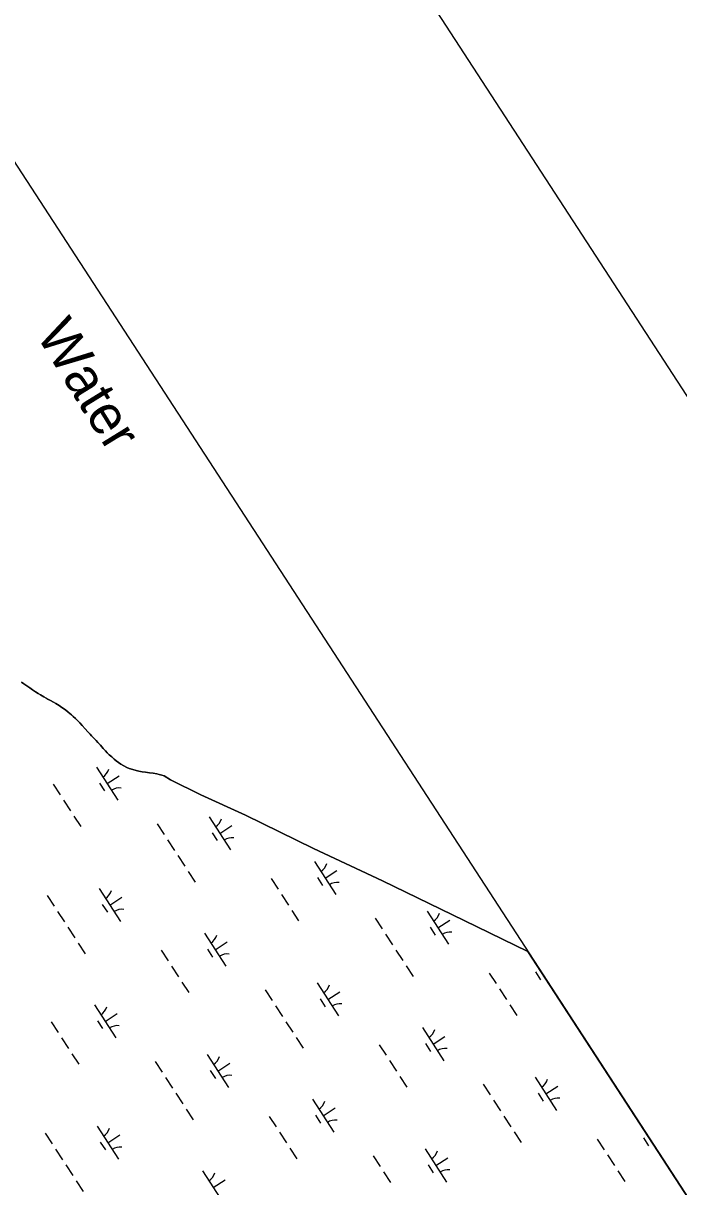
# Model space of a CAD drawing. Extents: x 3953924 to 3974542, y 193747 to 216192.
# Drawn here: x 3968321 to 3969152, y 206897 to 208370 of the extents above; entities that cross this region are included whole.
import ezdxf

# ---------------------------------------------------------------- set-up
doc = ezdxf.new("R2010")
doc.units = 0
for name, color, linetype in [('V-ANNO-SYMB', 7, 'Continuous'), ('V-GRID-FRAM', 7, 'Continuous'), ('V-RIVR-IDEN', 7, 'Continuous'), ('V-TOPO-SHOR', 7, 'Continuous'), ('V-WETL-SWMP', 7, 'Continuous')]:
    doc.layers.add(name, color=color, linetype=linetype)

msp = doc.modelspace()

# ---------------------------------------------------------------- linework, layer by layer
at = {"layer": 'V-ANNO-SYMB'}
msp.add_lwpolyline([(3955180.9, 208373.9), (3964205.1, 194510.7), (3973808.1, 200761.7), (3964783.9, 214624.9), (3955180.9, 208373.9)], dxfattribs=at)
at = {"layer": 'V-GRID-FRAM'}
msp.add_lwpolyline([(3964669.3, 213787.9), (3972946, 201072.9), (3966057, 196668.5), (3957950.8, 209463.9), (3964669.3, 213787.9)], dxfattribs=at)
at = {"layer": 'V-TOPO-SHOR'}
for points in [[(3968319.1, 207535.7), (3968322, 207533.5), (3968325.8, 207531), (3968329.8, 207528.3), (3968332.8, 207526.1), (3968336.7, 207523.6), (3968340.2, 207521.4), (3968343.3, 207519.6), (3968347.4, 207517.1), (3968350, 207515.6), (3968353.2, 207513.6), (3968355.9, 207512.3), (3968359.6, 207510.3), (3968362.6, 207508.6), (3968367, 207506), (3968370.4, 207503.7), (3968374.8, 207500.4), (3968378.3, 207497.7), (3968382.5, 207494.2), (3968384.7, 207492.1), (3968387.5, 207489.5), (3968390.4, 207486.7), (3968392.8, 207484.1), (3968396.1, 207480.6), (3968399.6, 207476.7), (3968403.2, 207472.7), (3968405.9, 207470), (3968407.9, 207467.6), (3968410.9, 207464.8), (3968413.7, 207461.6), (3968415.9, 207459.2), (3968419, 207455.7), (3968422.7, 207451.8), (3968425.5, 207448.6), (3968427.7, 207446.3), (3968430.4, 207443.8), (3968433.5, 207440.9), (3968436.7, 207438.2), (3968439.2, 207436.1), (3968442, 207433.9), (3968444.8, 207431.8), (3968448.8, 207429.6), (3968452.5, 207427.6), (3968455.6, 207426.5), (3968460, 207425)], [(3968460, 207425), (3968464.3, 207423.8), (3968467.9, 207423), (3968472, 207422.1), (3968476.4, 207421.6), (3968481.3, 207421), (3968486.1, 207420.4), (3968490.6, 207419.6), (3968493.6, 207418.9), (3968496.9, 207418), (3968499.9, 207417.1), (3968500.1, 207417), (3968507.8, 207411.8)], [(3968507.8, 207411.8), (3968546.6, 207393.1), (3968603, 207367.2), (3968689.4, 207324.8), (3968776.6, 207284)], [(3968776.6, 207284), (3968880, 207233.8), (3968961.1, 207194.7)]]:
    msp.add_lwpolyline(points, dxfattribs=at)
at = {"layer": 'V-WETL-SWMP'}
for p, q in [((3968322, 207533.5), (3968319.1, 207535.7)), ((3968325.8, 207531), (3968322, 207533.5)), ((3968329.8, 207528.3), (3968325.8, 207531)), ((3968332.8, 207526.1), (3968329.8, 207528.3)), ((3968336.7, 207523.6), (3968332.8, 207526.1)), ((3968340.2, 207521.4), (3968336.7, 207523.6)), ((3968343.3, 207519.6), (3968340.2, 207521.4)), ((3968347.4, 207517.1), (3968343.3, 207519.6)), ((3968353.2, 207513.6), (3968347.4, 207517.1)), ((3968355.9, 207512.3), (3968353.2, 207513.6)), ((3968359.6, 207510.3), (3968355.9, 207512.3)), ((3968362.6, 207508.6), (3968359.6, 207510.3)), ((3968367, 207506), (3968362.6, 207508.6)), ((3968370.4, 207503.7), (3968367, 207506)), ((3968374.8, 207500.4), (3968370.4, 207503.7)), ((3968378.3, 207497.7), (3968374.8, 207500.4)), ((3968382.5, 207494.2), (3968378.3, 207497.7)), ((3968384.7, 207492.1), (3968382.5, 207494.2)), ((3968387.5, 207489.5), (3968384.7, 207492.1)), ((3968390.4, 207486.7), (3968387.5, 207489.5)), ((3968392.8, 207484.1), (3968390.4, 207486.7)), ((3968396.1, 207480.6), (3968392.8, 207484.1)), ((3968399.6, 207476.7), (3968396.1, 207480.6)), ((3968403.2, 207472.7), (3968399.6, 207476.7)), ((3968405.9, 207470), (3968403.2, 207472.7)), ((3968407.9, 207467.6), (3968405.9, 207470)), ((3968410.9, 207464.8), (3968407.9, 207467.6)), ((3968413.7, 207461.6), (3968410.9, 207464.8)), ((3968415.9, 207459.2), (3968413.7, 207461.6)), ((3968419, 207455.7), (3968415.9, 207459.2)), ((3968422.7, 207451.8), (3968419, 207455.7)), ((3968425.5, 207448.6), (3968422.7, 207451.8)), ((3968427.7, 207446.3), (3968425.5, 207448.6)), ((3968430.4, 207443.8), (3968427.7, 207446.3)), ((3968433.5, 207440.9), (3968430.4, 207443.8)), ((3968436.7, 207438.2), (3968433.5, 207440.9)), ((3968439.2, 207436.1), (3968436.7, 207438.2)), ((3968442, 207433.9), (3968439.2, 207436.1)), ((3968414, 207428), (3968441.3, 207386.1)), ((3968444.8, 207431.8), (3968442, 207433.9)), ((3968448.8, 207429.6), (3968444.8, 207431.8)), ((3968452.5, 207427.6), (3968448.8, 207429.6)), ((3968455.6, 207426.5), (3968452.5, 207427.6)), ((3968460, 207425), (3968455.6, 207426.5)), ((3968464.3, 207423.8), (3968460, 207425)), ((3968467.9, 207423), (3968464.3, 207423.8)), ((3968472, 207422.1), (3968467.9, 207423)), ((3968476.4, 207421.6), (3968472, 207422.1)), ((3968481.3, 207421), (3968476.4, 207421.6)), ((3968486.1, 207420.4), (3968481.3, 207421)), ((3968490.6, 207419.6), (3968486.1, 207420.4)), ((3968493.6, 207418.9), (3968490.6, 207419.6)), ((3968359.2, 207406.4), (3968367.9, 207393)), ((3968417.9, 207407.9), (3968424.4, 207397.9)), ((3968427.6, 207407.1), (3968442.7, 207416.9)), ((3968496.9, 207418), (3968493.6, 207418.9)), ((3968499.9, 207417.1), (3968496.9, 207418)), ((3968500.1, 207417), (3968499.9, 207417.1)), ((3968507.8, 207411.8), (3968500.1, 207417)), ((3968546.6, 207393.1), (3968507.8, 207411.8)), ((3968603, 207367.2), (3968546.6, 207393.1)), ((3968372.3, 207386.3), (3968381, 207372.8)), ((3968385.4, 207366.1), (3968394.1, 207352.7)), ((3968556.9, 207365.1), (3968584.1, 207323.2)), ((3968689.4, 207324.8), (3968603, 207367.2)), ((3968491, 207356.2), (3968499.8, 207342.7)), ((3968570.5, 207344.1), (3968585.6, 207354)), ((3968504.1, 207336), (3968512.9, 207322.6)), ((3968560.8, 207345), (3968567.3, 207334.9)), ((3968776.6, 207284), (3968689.4, 207324.8)), ((3968517.2, 207315.9), (3968526, 207302.5)), ((3968690.3, 207308.5), (3968717.6, 207266.6)), ((3968530.3, 207295.8), (3968539.1, 207282.4)), ((3968635.5, 207286.8), (3968644.3, 207273.4)), ((3968694.2, 207288.3), (3968700.7, 207278.3)), ((3968703.9, 207287.5), (3968719, 207297.3)), ((3968417.5, 207274.3), (3968444.7, 207232.4)), ((3968880, 207233.8), (3968776.6, 207284)), ((3968351.6, 207265.4), (3968360.4, 207252)), ((3968431.1, 207253.4), (3968446.2, 207263.2)), ((3968648.6, 207266.7), (3968657.4, 207253.3)), ((3968364.7, 207245.3), (3968373.5, 207231.9)), ((3968421.4, 207254.2), (3968427.9, 207244.2)), ((3968661.7, 207246.6), (3968670.4, 207233.2)), ((3968833.2, 207245.5), (3968860.5, 207203.6)), ((3968767.4, 207236.6), (3968776.1, 207223.2)), ((3968846.8, 207224.6), (3968861.9, 207234.4)), ((3968961.1, 207194.7), (3968880, 207233.8)), ((3968377.8, 207225.2), (3968386.6, 207211.8)), ((3968550.9, 207217.7), (3968578.2, 207175.8)), ((3968780.4, 207216.5), (3968789.2, 207203.1)), ((3968837.1, 207225.4), (3968843.6, 207215.3)), ((3968390.9, 207205.1), (3968399.6, 207191.7)), ((3968564.5, 207196.8), (3968579.6, 207206.6)), ((3968496.1, 207196), (3968504.9, 207182.6)), ((3968554.8, 207197.6), (3968561.3, 207187.5)), ((3968793.5, 207196.4), (3968802.3, 207182.9)), ((3970976.1, 204099.2), (3968961.1, 207194.7)), ((3968509.2, 207175.9), (3968517.9, 207162.5)), ((3968806.6, 207176.2), (3968815.4, 207162.8)), ((3968970.5, 207168.8), (3968977, 207158.7)), ((3968522.3, 207155.8), (3968531, 207142.4)), ((3968693.8, 207154.8), (3968721, 207112.9)), ((3968911.8, 207167.2), (3968920.6, 207153.8)), ((3968628, 207145.8), (3968636.7, 207132.4)), ((3968707.4, 207133.8), (3968722.5, 207143.6)), ((3968924.9, 207147.1), (3968933.7, 207133.7)), ((3968411.5, 207127), (3968438.8, 207085.1)), ((3968641, 207125.7), (3968649.8, 207112.3)), ((3968697.7, 207134.6), (3968704.2, 207124.6)), ((3968938, 207127), (3968946.8, 207113.6)), ((3968425.1, 207106), (3968440.2, 207115.8)), ((3968356.7, 207105.3), (3968365.4, 207091.9)), ((3968415.4, 207106.8), (3968421.9, 207096.8)), ((3968654.1, 207105.6), (3968662.9, 207092.2)), ((3968827.2, 207098.2), (3968854.5, 207056.2)), ((3968369.8, 207085.2), (3968378.5, 207071.8)), ((3968667.2, 207085.5), (3968676, 207072.1)), ((3968840.8, 207077.2), (3968855.9, 207087)), ((3968772.4, 207076.5), (3968781.2, 207063.1)), ((3968831.1, 207078), (3968837.6, 207068)), ((3968382.9, 207065.1), (3968391.6, 207051.7)), ((3968488.5, 207055.1), (3968497.3, 207041.7)), ((3968554.4, 207064), (3968581.6, 207022.1)), ((3968568, 207043.1), (3968583.1, 207052.9)), ((3968785.5, 207056.4), (3968794.3, 207042.9)), ((3968558.3, 207043.9), (3968564.8, 207033.8)), ((3968798.6, 207036.2), (3968807.4, 207022.8)), ((3968501.6, 207035), (3968510.4, 207021.6)), ((3968904.3, 207026.3), (3968913, 207012.8)), ((3968970.1, 207035.2), (3968997.4, 206993.3)), ((3968983.7, 207014.2), (3968998.8, 207024.1)), ((3968514.7, 207014.9), (3968523.5, 207001.5)), ((3968687.8, 207007.4), (3968715.1, 206965.5)), ((3968974, 207015.1), (3968980.5, 207005)), ((3968527.8, 206994.7), (3968536.6, 206981.3)), ((3968701.4, 206986.5), (3968716.5, 206996.3)), ((3968917.4, 207006.1), (3968926.1, 206992.7)), ((3968633, 206985.7), (3968641.8, 206972.3)), ((3968691.7, 206987.3), (3968698.2, 206977.2)), ((3968930.4, 206986), (3968939.2, 206972.6)), ((3968349.1, 206964.3), (3968357.9, 206950.9)), ((3968415, 206973.3), (3968442.2, 206931.4)), ((3968646.1, 206965.6), (3968654.9, 206952.2)), ((3968943.5, 206965.9), (3968952.3, 206952.5)), ((3968418.9, 206953.1), (3968425.4, 206943.1)), ((3968428.6, 206952.3), (3968443.7, 206962.1)), ((3969048.7, 206956.9), (3969057.5, 206943.5)), ((3969107.4, 206958.4), (3969113.9, 206948.4)), ((3968362.2, 206944.2), (3968371, 206930.8)), ((3968659.2, 206945.5), (3968667.9, 206932.1)), ((3968764.9, 206935.5), (3968773.6, 206922.1)), ((3968830.7, 206944.4), (3968858, 206902.5)), ((3968844.3, 206923.5), (3968859.4, 206933.3)), ((3969061.8, 206936.8), (3969070.6, 206923.4)), ((3968375.3, 206924.1), (3968384.1, 206910.7)), ((3968834.6, 206924.3), (3968841.1, 206914.3)), ((3968388.4, 206904), (3968397.1, 206890.6)), ((3968548.4, 206916.7), (3968575.7, 206874.8)), ((3968562, 206895.7), (3968577.1, 206905.5)), ((3968778, 206915.4), (3968786.7, 206902)), ((3969074.9, 206916.7), (3969083.7, 206903.3))]:
    msp.add_line(p, q, dxfattribs=at)
for centre, start, end in [((3968412.7, 207430.4), 302.2901, 343.8338), ((3968442.9, 207384.1), 82.2901, 123.8337), ((3968555.6, 207367.4), 302.2901, 343.8338), ((3968585.8, 207321.1), 82.2901, 123.8337), ((3968689.1, 207310.8), 302.2901, 343.8338), ((3968719.2, 207264.5), 82.2901, 123.8337), ((3968416.2, 207276.7), 302.2901, 343.8338), ((3968446.4, 207230.4), 82.2901, 123.8337), ((3968831.9, 207247.8), 302.2901, 343.8338), ((3968549.6, 207220.1), 302.2901, 343.8338), ((3968862.1, 207201.5), 82.2901, 123.8337), ((3968579.8, 207173.8), 82.2901, 123.8337), ((3968692.5, 207157.1), 302.2901, 343.8338), ((3968722.7, 207110.8), 82.2901, 123.8337), ((3968410.2, 207129.3), 302.2901, 343.8338), ((3968440.4, 207083), 82.2901, 123.8337), ((3968826, 207100.5), 302.2901, 343.8338), ((3968856.1, 207054.2), 82.2901, 123.8337), ((3968553.1, 207066.3), 302.2901, 343.8338), ((3968583.3, 207020.1), 82.2901, 123.8337), ((3968968.9, 207037.5), 302.2901, 343.8338), ((3968999, 206991.2), 82.2901, 123.8337), ((3968686.6, 207009.7), 302.2901, 343.8338), ((3968716.7, 206963.4), 82.2901, 123.8337), ((3968413.7, 206975.6), 302.2901, 343.8338), ((3968443.9, 206929.3), 82.2901, 123.8337), ((3968829.4, 206946.8), 302.2901, 343.8338), ((3968547.2, 206919), 302.2901, 343.8338), ((3968859.6, 206900.5), 82.2901, 123.8337)]:
    msp.add_arc(centre, 17.6, start, end, dxfattribs=at)

# ---------------------------------------------------------------- texts
at = {"layer": 'V-RIVR-IDEN'}
msp.add_text('Water', height=50, rotation=301.6613, dxfattribs=at).set_placement((3968336.8, 207976.1))

doc.saveas('drawing.dxf')
